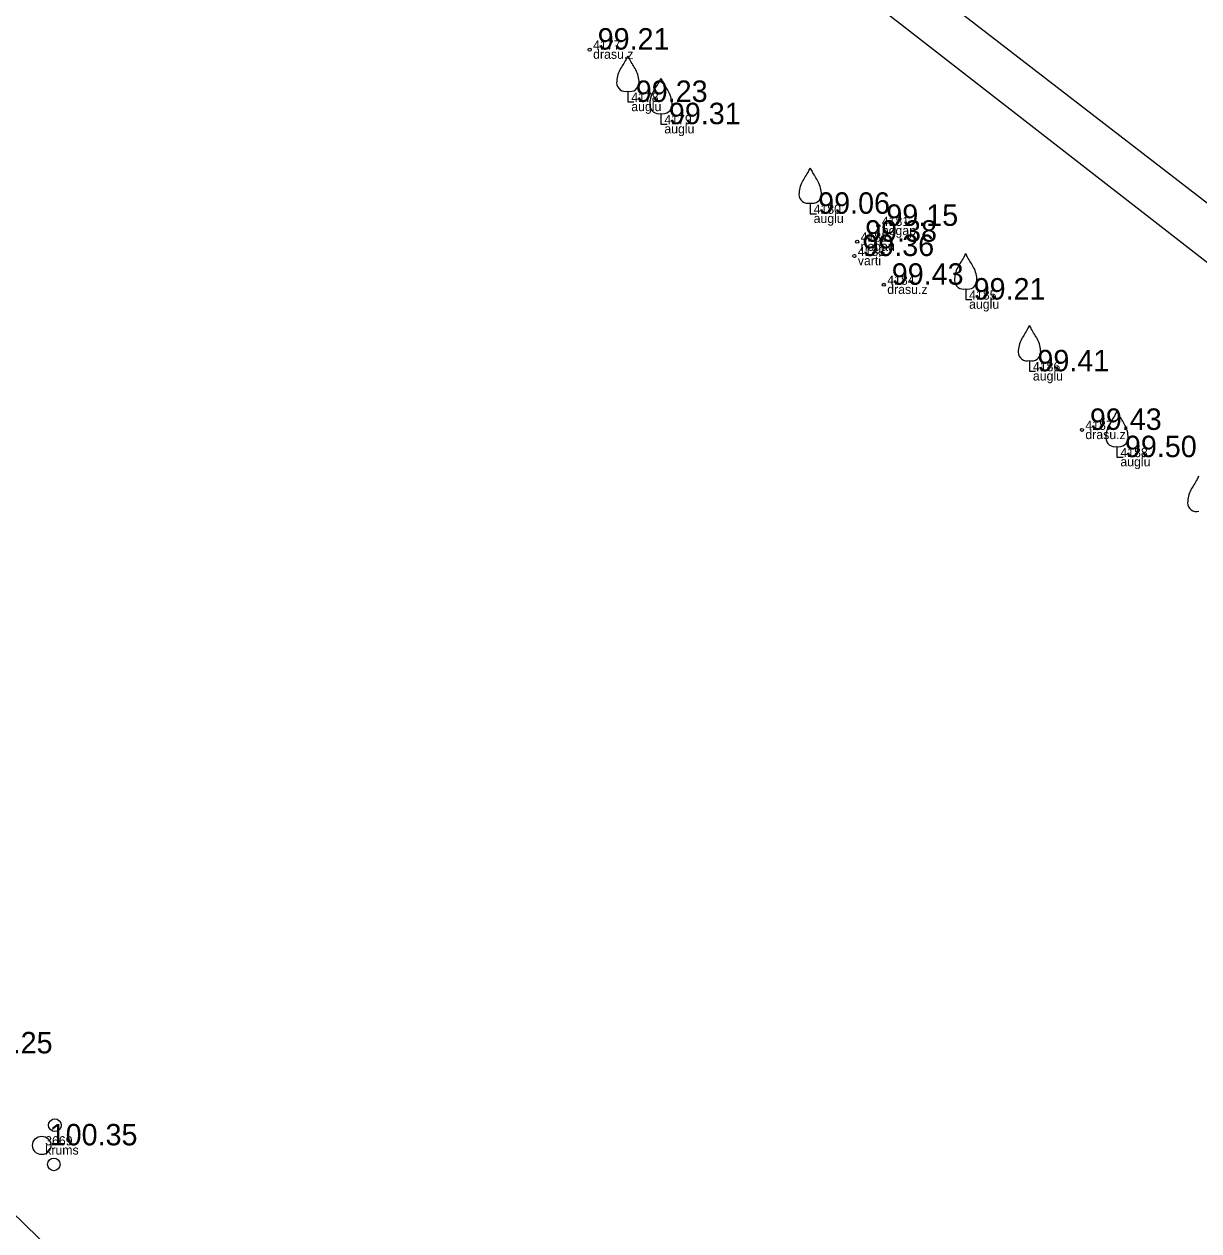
# Model space of a CAD drawing. Extents: x 614911 to 615803, y 262110 to 264311.
# Drawn here: x 615660.6 to 615698.92, y 264068.64 to 264108 of the extents above; entities that cross this region are included whole.
import ezdxf

# ---------------------------------------------------------------- set-up
doc = ezdxf.new("R2010")
doc.units = 0
for name, color, linetype in [('Level 1', 7, 'Continuous'), ('Level 37', 7, 'Continuous'), ('Level 53', 7, 'Continuous'), ('Level 54', 7, 'Continuous'), ('Level 57', 7, 'Continuous'), ('Level 58', 7, 'Continuous')]:
    doc.layers.add(name, color=color, linetype=linetype)

msp = doc.modelspace()

# ---------------------------------------------------------------- linework, layer by layer
at = {"layer": 'Level 1'}
for p, q in [((615680.29, 264105.817), (615680.29, 264105.465)), ((615680.29, 264105.465), (615680.49, 264105.465)), ((615681.369, 264105.091), (615681.369, 264104.739)), ((615681.369, 264104.739), (615681.569, 264104.739)), ((615686.239, 264102.169), (615686.239, 264101.817)), ((615686.239, 264101.817), (615686.439, 264101.817)), ((615691.311, 264099.371), (615691.311, 264099.019)), ((615691.311, 264099.019), (615691.511, 264099.019)), ((615693.392, 264097.031), (615693.392, 264096.679)), ((615693.392, 264096.679), (615693.592, 264096.679)), ((615696.246, 264094.231), (615696.246, 264093.879)), ((615696.246, 264093.879), (615696.446, 264093.879))]:
    msp.add_line(p, q, dxfattribs=at)
for centre, radius in [((615661.597, 264072.091), 0.207), ((615661.17, 264071.431), 0.301), ((615661.565, 264070.811), 0.205)]:
    msp.add_circle(centre, radius, dxfattribs=at)
for centre, radius, start, end in [((615692.915, 264099.069), 14.88, 148.4844, 149.9901), ((615679.873, 264107.103), 0.439, 324.3837, 341.712), ((615680.707, 264107.103), 0.439, 198.288, 215.6163), ((615667.665, 264099.069), 14.88, 30.0099, 31.5156), ((615680.814, 264106.09), 0.89, 151.757, 179.9138), ((615679.766, 264106.09), 0.89, 0.0862, 28.243), ((615680.214, 264106.096), 0.29, 181.0782, 285.2823), ((615680.366, 264106.096), 0.29, 254.7177, 358.9218), ((615693.994, 264098.343), 14.88, 148.4844, 149.9901), ((615680.952, 264106.377), 0.439, 324.3837, 341.712), ((615681.786, 264106.377), 0.439, 198.288, 215.6163), ((615668.744, 264098.343), 14.88, 30.0099, 31.5156), ((615681.893, 264105.364), 0.89, 151.757, 179.9138), ((615680.845, 264105.364), 0.89, 0.0862, 28.243), ((615681.293, 264105.37), 0.29, 181.0782, 285.2823), ((615681.445, 264105.37), 0.29, 254.7177, 358.9218), ((615698.864, 264095.421), 14.88, 148.4844, 149.9901), ((615685.822, 264103.455), 0.439, 324.3837, 341.712), ((615686.656, 264103.455), 0.439, 198.288, 215.6163), ((615673.614, 264095.421), 14.88, 30.0099, 31.5156), ((615686.763, 264102.442), 0.89, 151.757, 179.9138), ((615685.715, 264102.442), 0.89, 0.0862, 28.243), ((615686.163, 264102.448), 0.29, 181.0782, 285.2823), ((615686.315, 264102.448), 0.29, 254.7177, 358.9218), ((615690.894, 264100.657), 0.439, 324.3837, 341.712), ((615691.728, 264100.657), 0.439, 198.288, 215.6163), ((615691.835, 264099.644), 0.89, 151.757, 179.9138), ((615703.936, 264092.623), 14.88, 148.4844, 149.9901), ((615678.686, 264092.623), 14.88, 30.0099, 31.5156), ((615690.787, 264099.644), 0.89, 0.0862, 28.243), ((615691.235, 264099.65), 0.29, 181.0782, 285.2823), ((615691.387, 264099.65), 0.29, 254.7177, 358.9218), ((615706.017, 264090.283), 14.88, 148.4844, 149.9901), ((615692.975, 264098.317), 0.439, 324.3837, 341.712), ((615693.809, 264098.317), 0.439, 198.288, 215.6163), ((615680.767, 264090.283), 14.88, 30.0099, 31.5156), ((615693.916, 264097.304), 0.89, 151.757, 179.9138), ((615692.868, 264097.304), 0.89, 0.0862, 28.243), ((615693.316, 264097.31), 0.29, 181.0782, 285.2823), ((615693.468, 264097.31), 0.29, 254.7177, 358.9218), ((615695.829, 264095.517), 0.439, 324.3837, 341.712), ((615696.663, 264095.517), 0.439, 198.288, 215.6163), ((615696.77, 264094.504), 0.89, 151.757, 179.9138), ((615708.871, 264087.483), 14.88, 148.4844, 149.9901), ((615683.621, 264087.483), 14.88, 30.0099, 31.5156), ((615695.722, 264094.504), 0.89, 0.0862, 28.243), ((615696.17, 264094.51), 0.29, 181.0782, 285.2823), ((615696.322, 264094.51), 0.29, 254.7177, 358.9218), ((615711.543, 264085.369), 14.88, 148.4844, 149.9901), ((615698.501, 264093.403), 0.439, 324.3837, 341.712), ((615699.442, 264092.39), 0.89, 151.757, 179.9138), ((615698.842, 264092.396), 0.29, 181.0782, 285.2823)]:
    msp.add_arc(centre, radius, start, end, dxfattribs=at)
at = {"layer": 'Level 37'}
for points in [[(615625.063, 264106.562), (615623.229, 264104.588), (615622.747, 264105.634), (615621.37, 264105.71), (615619.131, 264107.71), (615616.734, 264111.901), (615616.748, 264121.153), (615617.254, 264127.034), (615619.687, 264135.318), (615625.708, 264142.666), (615632.784, 264145.968), (615640.605, 264144.932), (615648.422, 264143.136), (615670.375, 264124.985), (615688.06, 264110.762), (615709.564, 264094.167), (615727.03, 264081.038), (615738.779, 264072.364)], [(615737.997, 264071.23), (615726.411, 264079.821), (615708.486, 264093), (615687.279, 264109.494), (615669.461, 264123.776), (615649.379, 264140.934), (615645.431, 264143.727)], [(615672.934, 264057.904), (615662.431, 264067.076), (615655.128, 264074.202), (615650.98, 264078.306), (615651.376, 264079.47), (615652.711, 264080.317)]]:
    msp.add_lwpolyline(points, dxfattribs=at)
at = {"layer": 'Level 57'}
for centre in [(615679.046, 264107.172), (615688.463, 264101.423), (615687.771, 264100.907), (615687.68, 264100.439), (615688.64, 264099.502), (615695.104, 264094.768)]:
    msp.add_circle(centre, 0.05, dxfattribs=at)
at = {"layer": 'Level 58'}
for centre in [(615679.046, 264107.172), (615688.463, 264101.423), (615687.771, 264100.907), (615687.68, 264100.439), (615688.64, 264099.502), (615695.104, 264094.768)]:
    msp.add_circle(centre, 0.05, dxfattribs=at)

# ---------------------------------------------------------------- texts
at = {"layer": 'Level 53'}
for s, p in [(' drasu.z', (615679.046, 264106.872)), (' auglu', (615680.29, 264105.165)), (' auglu', (615681.369, 264104.439)), (' auglu', (615686.239, 264101.517)), (' nogap', (615688.463, 264101.123)), (' nogau', (615687.771, 264100.607)), (' varti', (615687.68, 264100.139)), (' drasu.z', (615688.64, 264099.202)), (' auglu', (615691.311, 264098.719)), (' auglu', (615693.392, 264096.379)), (' drasu.z', (615695.104, 264094.468)), (' auglu', (615696.246, 264093.579)), (' krums', (615661.17, 264071.131))]:
    msp.add_text(s, height=0.3, dxfattribs=at).set_placement(p)
at = {"layer": 'Level 54'}
for s, p in [(' 4177', (615679.046, 264107.172)), (' 4178', (615680.29, 264105.465)), (' 4179', (615681.369, 264104.739)), (' 4180', (615686.239, 264101.817)), (' 4181', (615688.463, 264101.423)), (' 4182', (615687.771, 264100.907)), (' 4183', (615687.68, 264100.439)), (' 4184', (615688.64, 264099.502)), (' 4185', (615691.311, 264099.019)), (' 4186', (615693.392, 264096.679)), (' 4187', (615695.104, 264094.768)), (' 4188', (615696.246, 264093.879)), (' 3669', (615661.17, 264071.431))]:
    msp.add_text(s, height=0.3, dxfattribs=at).set_placement(p)
at = {"layer": 'Level 58'}
for s, p in [(' 99.21', (615679.046, 264107.172)), (' 99.23', (615680.29, 264105.465)), (' 99.31', (615681.369, 264104.739)), (' 99.06', (615686.239, 264101.817)), (' 99.15', (615688.463, 264101.423)), (' 99.38', (615687.771, 264100.907)), (' 99.36', (615687.68, 264100.439)), (' 99.43', (615688.64, 264099.502)), (' 99.21', (615691.311, 264099.019)), (' 99.41', (615693.392, 264096.679)), (' 99.43', (615695.104, 264094.768)), (' 99.50', (615696.246, 264093.879)), (' 100.25', (615658.4, 264074.432)), (' 100.35', (615661.17, 264071.431))]:
    msp.add_text(s, height=0.7, dxfattribs=at).set_placement(p)

doc.saveas('drawing.dxf')
